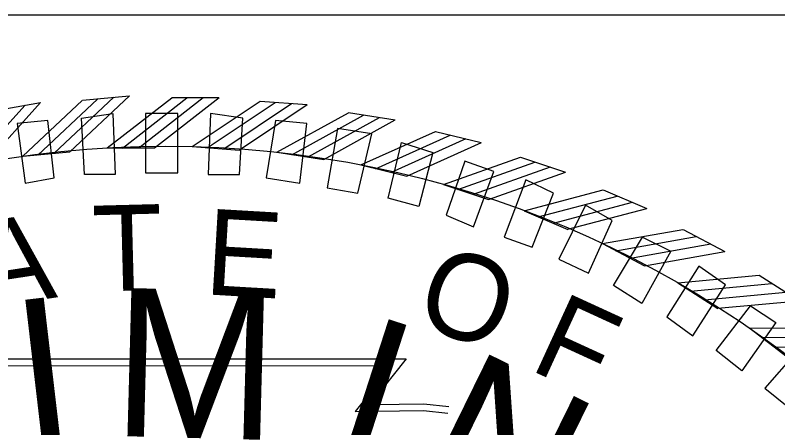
# Model space of a CAD drawing. Extents: x 16 to 1228740, y 11 to 152440.
# Drawn here: x 17.7544 to 17.8153, y 10.9657 to 10.9986 of the extents above; entities that cross this region are included whole.
import ezdxf

# ---------------------------------------------------------------- set-up
doc = ezdxf.new("R2010")
doc.units = 0
for name, color, linetype in [('B_Preliminary', 7, 'Continuous'), ('B_StampERBB', 7, 'Continuous'), ('B_StampHSS', 7, 'Continuous'), ('B_StampJSB', 7, 'Continuous'), ('B_StampSCR', 7, 'Continuous'), ('B_StampSFH', 7, 'Continuous'), ('R_No Plot', 7, 'Continuous')]:
    doc.layers.add(name, color=color, linetype=linetype)

msp = doc.modelspace()

# ---------------------------------------------------------------- linework, layer by layer
at = {"layer": 'B_Preliminary'}
for p, q in [((17.75971, 10.990408), (17.76221, 10.990783)), ((17.76221, 10.990783), (17.762402, 10.985908)), ((17.767402, 10.990783), (17.764835, 10.990783)), ((17.764835, 10.990783), (17.764835, 10.986033)), ((17.767402, 10.986033), (17.767402, 10.990783)), ((17.770027, 10.990783), (17.769835, 10.985908)), ((17.772585, 10.990408), (17.770027, 10.990783)), ((17.757027, 10.990224), (17.754585, 10.989974)), ((17.754585, 10.989974), (17.75521, 10.985224)), ((17.757527, 10.985658), (17.757027, 10.990224)), ((17.75996, 10.985908), (17.75971, 10.990408)), ((17.772335, 10.985908), (17.772585, 10.990408)), ((17.77521, 10.990224), (17.77446, 10.985658)), ((17.77771, 10.989974), (17.77521, 10.990224)), ((17.777152, 10.985224), (17.77771, 10.989974)), ((17.780152, 10.989599), (17.779335, 10.984849)), ((17.782902, 10.989158), (17.780152, 10.989599)), ((17.781777, 10.984408), (17.782902, 10.989158)), ((17.78421, 10.984033), (17.785277, 10.988474)), ((17.785277, 10.988474), (17.787777, 10.987658)), ((17.787777, 10.987658), (17.786652, 10.983349)), ((17.790335, 10.986974), (17.788835, 10.982658)), ((17.792652, 10.986158), (17.790335, 10.986974)), ((17.75521, 10.985224), (17.757527, 10.985658)), ((17.762402, 10.985908), (17.75996, 10.985908)), ((17.764835, 10.986033), (17.767402, 10.986033)), ((17.769835, 10.985908), (17.772335, 10.985908)), ((17.77446, 10.985658), (17.777152, 10.985224)), ((17.791027, 10.981724), (17.792652, 10.986158)), ((17.79521, 10.985474), (17.79346, 10.980908)), ((17.797402, 10.984408), (17.79521, 10.985474)), ((17.779335, 10.984849), (17.781777, 10.984408)), ((17.79571, 10.980099), (17.797402, 10.984408)), ((17.786652, 10.983349), (17.78421, 10.984033)), ((17.79996, 10.983474), (17.797835, 10.979158)), ((17.802085, 10.982224), (17.79996, 10.983474)), ((17.788835, 10.982658), (17.791027, 10.981724)), ((17.80021, 10.978033), (17.802085, 10.982224)), ((17.79346, 10.980908), (17.79571, 10.980099)), ((17.80221, 10.977033), (17.804527, 10.980908)), ((17.804527, 10.980908), (17.806777, 10.979783)), ((17.806777, 10.979783), (17.80446, 10.975599)), ((17.797835, 10.979158), (17.80021, 10.978033)), ((17.809027, 10.978599), (17.80646, 10.974533)), ((17.811152, 10.977099), (17.809027, 10.978599)), ((17.808527, 10.973033), (17.811152, 10.977099)), ((17.80446, 10.975599), (17.80221, 10.977033)), ((17.810402, 10.971849), (17.813152, 10.975408)), ((17.813152, 10.975408), (17.815152, 10.974099)), ((17.80646, 10.974533), (17.808527, 10.973033)), ((17.815152, 10.974099), (17.81246, 10.970224)), ((17.81746, 10.972474), (17.814277, 10.968849)), ((17.81246, 10.970224), (17.810402, 10.971849)), ((17.814277, 10.968849), (17.81621, 10.967283))]:
    msp.add_line(p, q, dxfattribs=at)
at = {"layer": 'B_StampERBB'}
for p, q in [((17.759782, 10.99184), (17.763536, 10.992186)), ((17.766921, 10.99205), (17.770691, 10.99205)), ((17.773983, 10.991767), (17.777742, 10.991491)), ((17.752726, 10.990997), (17.756438, 10.991651)), ((17.78103, 10.990852), (17.784754, 10.990266)), ((17.787978, 10.989358), (17.791641, 10.988467)), ((17.761776, 10.988038), (17.765555, 10.988038)), ((17.768557, 10.988144), (17.772326, 10.987867)), ((17.755027, 10.987373), (17.75879, 10.98772)), ((17.775324, 10.987689), (17.779057, 10.987102)), ((17.794778, 10.987296), (17.798355, 10.986105)), ((17.78203, 10.986678), (17.785702, 10.985784)), ((17.78863, 10.985115), (17.792215, 10.983921)), ((17.801385, 10.984679), (17.804852, 10.983196)), ((17.795078, 10.983014), (17.798552, 10.981528)), ((17.807754, 10.981525), (17.811086, 10.979762)), ((17.80133, 10.980386), (17.80467, 10.978619)), ((17.81384, 10.977856), (17.817015, 10.975824)), ((17.807344, 10.977252), (17.810526, 10.975214)), ((17.813079, 10.973632), (17.816082, 10.971338))]:
    msp.add_line(p, q, dxfattribs=at)
for points in [[(17.755023, 10.987369), (17.759777, 10.991836)], [(17.756232, 10.987469), (17.760986, 10.991936)], [(17.757534, 10.987618), (17.762288, 10.992085)], [(17.758785, 10.987722), (17.763539, 10.992189)], [(17.761772, 10.988035), (17.766915, 10.992046)], [(17.762985, 10.988024), (17.768129, 10.992035)], [(17.764295, 10.988053), (17.769438, 10.992064)], [(17.765551, 10.988041), (17.770694, 10.992053)], [(17.768553, 10.988141), (17.773977, 10.991764)], [(17.769762, 10.988041), (17.775186, 10.991664)], [(17.750833, 10.986604), (17.755202, 10.991448)], [(17.752072, 10.986811), (17.756441, 10.991655)], [(17.77107, 10.987973), (17.776494, 10.991597)], [(17.772322, 10.98787), (17.777746, 10.991493)], [(17.775319, 10.987687), (17.781024, 10.99085)], [(17.776516, 10.987487), (17.782221, 10.99065)], [(17.777814, 10.987312), (17.783519, 10.990475)], [(17.779053, 10.987105), (17.784758, 10.990268)], [(17.782025, 10.986675), (17.787972, 10.989356)], [(17.783201, 10.986377), (17.789148, 10.989058)], [(17.78448, 10.986096), (17.790427, 10.988777)], [(17.785698, 10.985787), (17.791645, 10.988468)], [(17.788624, 10.985113), (17.794772, 10.987294)], [(17.789772, 10.984719), (17.79592, 10.9869)], [(17.791024, 10.984333), (17.797171, 10.986514)], [(17.792211, 10.983925), (17.798359, 10.986106)], [(17.795072, 10.983012), (17.801379, 10.984678)], [(17.796183, 10.982525), (17.80249, 10.98419)], [(17.797399, 10.982036), (17.803706, 10.983702)], [(17.798549, 10.981532), (17.804856, 10.983198)], [(17.801324, 10.980385), (17.807747, 10.981525)], [(17.802392, 10.979808), (17.808815, 10.980947)], [(17.803563, 10.979221), (17.809986, 10.98036)], [(17.804667, 10.978623), (17.81109, 10.979762)], [(17.807338, 10.977251), (17.813834, 10.977856)], [(17.808354, 10.976588), (17.814849, 10.977193)], [(17.809473, 10.975906), (17.815968, 10.976511)], [(17.810524, 10.975219), (17.817019, 10.975824)], [(17.813073, 10.973632), (17.819596, 10.973698)], [(17.814031, 10.972886), (17.820554, 10.972953)], [(17.815089, 10.972114), (17.821612, 10.972181)], [(17.752875, 10.966818), (17.750865, 10.97117), (17.785635, 10.97119), (17.78273, 10.96754), (17.785092, 10.967571), (17.787065, 10.967597), (17.789037, 10.967382)], [(17.753375, 10.967049), (17.751726, 10.97062), (17.784493, 10.970639), (17.781576, 10.966974), (17.785099, 10.96702), (17.787039, 10.967045), (17.788977, 10.966834)]]:
    msp.add_lwpolyline(points, dxfattribs=at)
at = {"layer": 'B_StampHSS'}
for p, q in [((17.759782, 10.99184), (17.763536, 10.992186)), ((17.766921, 10.99205), (17.770691, 10.99205)), ((17.773983, 10.991767), (17.777742, 10.991491)), ((17.752726, 10.990997), (17.756438, 10.991651)), ((17.78103, 10.990852), (17.784754, 10.990266)), ((17.787978, 10.989358), (17.791641, 10.988467)), ((17.761776, 10.988038), (17.765555, 10.988038)), ((17.768557, 10.988144), (17.772326, 10.987867)), ((17.755027, 10.987373), (17.75879, 10.98772)), ((17.775324, 10.987689), (17.779057, 10.987102)), ((17.794778, 10.987296), (17.798355, 10.986105)), ((17.78203, 10.986678), (17.785702, 10.985784)), ((17.78863, 10.985115), (17.792215, 10.983921)), ((17.801385, 10.984679), (17.804852, 10.983196)), ((17.795078, 10.983014), (17.798552, 10.981528)), ((17.807754, 10.981525), (17.811086, 10.979762)), ((17.80133, 10.980386), (17.80467, 10.978619)), ((17.81384, 10.977856), (17.817015, 10.975824)), ((17.807344, 10.977252), (17.810526, 10.975214)), ((17.813079, 10.973632), (17.816082, 10.971338))]:
    msp.add_line(p, q, dxfattribs=at)
for points in [[(17.755023, 10.987369), (17.759777, 10.991836)], [(17.756232, 10.987469), (17.760986, 10.991936)], [(17.757534, 10.987618), (17.762288, 10.992085)], [(17.758785, 10.987722), (17.763539, 10.992189)], [(17.761772, 10.988035), (17.766915, 10.992046)], [(17.762985, 10.988024), (17.768129, 10.992035)], [(17.764295, 10.988053), (17.769438, 10.992064)], [(17.765551, 10.988041), (17.770694, 10.992053)], [(17.768553, 10.988141), (17.773977, 10.991764)], [(17.769762, 10.988041), (17.775186, 10.991664)], [(17.750833, 10.986604), (17.755202, 10.991448)], [(17.752072, 10.986811), (17.756441, 10.991655)], [(17.77107, 10.987973), (17.776494, 10.991597)], [(17.772322, 10.98787), (17.777746, 10.991493)], [(17.775319, 10.987687), (17.781024, 10.99085)], [(17.776516, 10.987487), (17.782221, 10.99065)], [(17.777814, 10.987312), (17.783519, 10.990475)], [(17.779053, 10.987105), (17.784758, 10.990268)], [(17.782025, 10.986675), (17.787972, 10.989356)], [(17.783201, 10.986377), (17.789148, 10.989058)], [(17.78448, 10.986096), (17.790427, 10.988777)], [(17.785698, 10.985787), (17.791645, 10.988468)], [(17.788624, 10.985113), (17.794772, 10.987294)], [(17.789772, 10.984719), (17.79592, 10.9869)], [(17.791024, 10.984333), (17.797171, 10.986514)], [(17.792211, 10.983925), (17.798359, 10.986106)], [(17.795072, 10.983012), (17.801379, 10.984678)], [(17.796183, 10.982525), (17.80249, 10.98419)], [(17.797399, 10.982036), (17.803706, 10.983702)], [(17.798549, 10.981532), (17.804856, 10.983198)], [(17.801324, 10.980385), (17.807747, 10.981525)], [(17.802392, 10.979808), (17.808815, 10.980947)], [(17.803563, 10.979221), (17.809986, 10.98036)], [(17.804667, 10.978623), (17.81109, 10.979762)], [(17.807338, 10.977251), (17.813834, 10.977856)], [(17.808354, 10.976588), (17.814849, 10.977193)], [(17.809473, 10.975906), (17.815968, 10.976511)], [(17.810524, 10.975219), (17.817019, 10.975824)], [(17.813073, 10.973632), (17.819596, 10.973698)], [(17.814031, 10.972886), (17.820554, 10.972953)], [(17.815089, 10.972114), (17.821612, 10.972181)], [(17.752875, 10.966818), (17.750865, 10.97117), (17.785635, 10.97119), (17.78273, 10.96754), (17.785092, 10.967571), (17.787065, 10.967597), (17.789037, 10.967382)], [(17.753375, 10.967049), (17.751726, 10.97062), (17.784493, 10.970639), (17.781576, 10.966974), (17.785099, 10.96702), (17.787039, 10.967045), (17.788977, 10.966834)]]:
    msp.add_lwpolyline(points, dxfattribs=at)
at = {"layer": 'B_StampJSB'}
for p, q in [((17.759782, 10.99184), (17.763536, 10.992186)), ((17.766921, 10.99205), (17.770691, 10.99205)), ((17.773983, 10.991767), (17.777742, 10.991491)), ((17.752726, 10.990997), (17.756438, 10.991651)), ((17.78103, 10.990852), (17.784754, 10.990266)), ((17.787978, 10.989358), (17.791641, 10.988467)), ((17.761776, 10.988038), (17.765555, 10.988038)), ((17.768557, 10.988144), (17.772326, 10.987867)), ((17.755027, 10.987373), (17.75879, 10.98772)), ((17.775324, 10.987689), (17.779057, 10.987102)), ((17.794778, 10.987296), (17.798355, 10.986105)), ((17.78203, 10.986678), (17.785702, 10.985784)), ((17.78863, 10.985115), (17.792215, 10.983921)), ((17.801385, 10.984679), (17.804852, 10.983196)), ((17.795078, 10.983014), (17.798552, 10.981528)), ((17.807754, 10.981525), (17.811086, 10.979762)), ((17.80133, 10.980386), (17.80467, 10.978619)), ((17.81384, 10.977856), (17.817015, 10.975824)), ((17.807344, 10.977252), (17.810526, 10.975214)), ((17.813079, 10.973632), (17.816082, 10.971338))]:
    msp.add_line(p, q, dxfattribs=at)
for points in [[(17.755023, 10.987369), (17.759777, 10.991836)], [(17.756232, 10.987469), (17.760986, 10.991936)], [(17.757534, 10.987618), (17.762288, 10.992085)], [(17.758785, 10.987722), (17.763539, 10.992189)], [(17.761772, 10.988035), (17.766915, 10.992046)], [(17.762985, 10.988024), (17.768129, 10.992035)], [(17.764295, 10.988053), (17.769438, 10.992064)], [(17.765551, 10.988041), (17.770694, 10.992053)], [(17.768553, 10.988141), (17.773977, 10.991764)], [(17.769762, 10.988041), (17.775186, 10.991664)], [(17.750833, 10.986604), (17.755202, 10.991448)], [(17.752072, 10.986811), (17.756441, 10.991655)], [(17.77107, 10.987973), (17.776494, 10.991597)], [(17.772322, 10.98787), (17.777746, 10.991493)], [(17.775319, 10.987687), (17.781024, 10.99085)], [(17.776516, 10.987487), (17.782221, 10.99065)], [(17.777814, 10.987312), (17.783519, 10.990475)], [(17.779053, 10.987105), (17.784758, 10.990268)], [(17.782025, 10.986675), (17.787972, 10.989356)], [(17.783201, 10.986377), (17.789148, 10.989058)], [(17.78448, 10.986096), (17.790427, 10.988777)], [(17.785698, 10.985787), (17.791645, 10.988468)], [(17.788624, 10.985113), (17.794772, 10.987294)], [(17.789772, 10.984719), (17.79592, 10.9869)], [(17.791024, 10.984333), (17.797171, 10.986514)], [(17.792211, 10.983925), (17.798359, 10.986106)], [(17.795072, 10.983012), (17.801379, 10.984678)], [(17.796183, 10.982525), (17.80249, 10.98419)], [(17.797399, 10.982036), (17.803706, 10.983702)], [(17.798549, 10.981532), (17.804856, 10.983198)], [(17.801324, 10.980385), (17.807747, 10.981525)], [(17.802392, 10.979808), (17.808815, 10.980947)], [(17.803563, 10.979221), (17.809986, 10.98036)], [(17.804667, 10.978623), (17.81109, 10.979762)], [(17.807338, 10.977251), (17.813834, 10.977856)], [(17.808354, 10.976588), (17.814849, 10.977193)], [(17.809473, 10.975906), (17.815968, 10.976511)], [(17.810524, 10.975219), (17.817019, 10.975824)], [(17.813073, 10.973632), (17.819596, 10.973698)], [(17.814031, 10.972886), (17.820554, 10.972953)], [(17.815089, 10.972114), (17.821612, 10.972181)], [(17.752875, 10.966818), (17.750865, 10.97117), (17.785635, 10.97119), (17.78273, 10.96754), (17.785092, 10.967571), (17.787065, 10.967597), (17.789037, 10.967382)], [(17.753375, 10.967049), (17.751726, 10.97062), (17.784493, 10.970639), (17.781576, 10.966974), (17.785099, 10.96702), (17.787039, 10.967045), (17.788977, 10.966834)]]:
    msp.add_lwpolyline(points, dxfattribs=at)
msp.add_circle((17.766447, 10.906117), 0.082054, dxfattribs=at)
at = {"layer": 'B_StampSCR'}
for p, q in [((17.759782, 10.99184), (17.763536, 10.992186)), ((17.766921, 10.99205), (17.770691, 10.99205)), ((17.773983, 10.991767), (17.777742, 10.991491)), ((17.752726, 10.990997), (17.756438, 10.991651)), ((17.78103, 10.990852), (17.784754, 10.990266)), ((17.787978, 10.989358), (17.791641, 10.988467)), ((17.761776, 10.988038), (17.765555, 10.988038)), ((17.768557, 10.988144), (17.772326, 10.987867)), ((17.755027, 10.987373), (17.75879, 10.98772)), ((17.775324, 10.987689), (17.779057, 10.987102)), ((17.794778, 10.987296), (17.798355, 10.986105)), ((17.78203, 10.986678), (17.785702, 10.985784)), ((17.78863, 10.985115), (17.792215, 10.983921)), ((17.801385, 10.984679), (17.804852, 10.983196)), ((17.795078, 10.983014), (17.798552, 10.981528)), ((17.807754, 10.981525), (17.811086, 10.979762)), ((17.80133, 10.980386), (17.80467, 10.978619)), ((17.81384, 10.977856), (17.817015, 10.975824)), ((17.807344, 10.977252), (17.810526, 10.975214)), ((17.813079, 10.973632), (17.816082, 10.971338))]:
    msp.add_line(p, q, dxfattribs=at)
for points in [[(17.755023, 10.987369), (17.759777, 10.991836)], [(17.756232, 10.987469), (17.760986, 10.991936)], [(17.757534, 10.987618), (17.762288, 10.992085)], [(17.758785, 10.987722), (17.763539, 10.992189)], [(17.761772, 10.988035), (17.766915, 10.992046)], [(17.762985, 10.988024), (17.768129, 10.992035)], [(17.764295, 10.988053), (17.769438, 10.992064)], [(17.765551, 10.988041), (17.770694, 10.992053)], [(17.768553, 10.988141), (17.773977, 10.991764)], [(17.769762, 10.988041), (17.775186, 10.991664)], [(17.750833, 10.986604), (17.755202, 10.991448)], [(17.752072, 10.986811), (17.756441, 10.991655)], [(17.77107, 10.987973), (17.776494, 10.991597)], [(17.772322, 10.98787), (17.777746, 10.991493)], [(17.775319, 10.987687), (17.781024, 10.99085)], [(17.776516, 10.987487), (17.782221, 10.99065)], [(17.777814, 10.987312), (17.783519, 10.990475)], [(17.779053, 10.987105), (17.784758, 10.990268)], [(17.782025, 10.986675), (17.787972, 10.989356)], [(17.783201, 10.986377), (17.789148, 10.989058)], [(17.78448, 10.986096), (17.790427, 10.988777)], [(17.785698, 10.985787), (17.791645, 10.988468)], [(17.788624, 10.985113), (17.794772, 10.987294)], [(17.789772, 10.984719), (17.79592, 10.9869)], [(17.791024, 10.984333), (17.797171, 10.986514)], [(17.792211, 10.983925), (17.798359, 10.986106)], [(17.795072, 10.983012), (17.801379, 10.984678)], [(17.796183, 10.982525), (17.80249, 10.98419)], [(17.797399, 10.982036), (17.803706, 10.983702)], [(17.798549, 10.981532), (17.804856, 10.983198)], [(17.801324, 10.980385), (17.807747, 10.981525)], [(17.802392, 10.979808), (17.808815, 10.980947)], [(17.803563, 10.979221), (17.809986, 10.98036)], [(17.804667, 10.978623), (17.81109, 10.979762)], [(17.807338, 10.977251), (17.813834, 10.977856)], [(17.808354, 10.976588), (17.814849, 10.977193)], [(17.809473, 10.975906), (17.815968, 10.976511)], [(17.810524, 10.975219), (17.817019, 10.975824)], [(17.813073, 10.973632), (17.819596, 10.973698)], [(17.814031, 10.972886), (17.820554, 10.972953)], [(17.815089, 10.972114), (17.821612, 10.972181)], [(17.752875, 10.966818), (17.750865, 10.97117), (17.785635, 10.97119), (17.78273, 10.96754), (17.785092, 10.967571), (17.787065, 10.967597), (17.789037, 10.967382)], [(17.753375, 10.967049), (17.751726, 10.97062), (17.784493, 10.970639), (17.781576, 10.966974), (17.785099, 10.96702), (17.787039, 10.967045), (17.788977, 10.966834)]]:
    msp.add_lwpolyline(points, dxfattribs=at)
at = {"layer": 'B_StampSFH'}
for p, q in [((17.759782, 10.99184), (17.763536, 10.992186)), ((17.766921, 10.99205), (17.770691, 10.99205)), ((17.773983, 10.991767), (17.777742, 10.991491)), ((17.752726, 10.990997), (17.756438, 10.991651)), ((17.78103, 10.990852), (17.784754, 10.990266)), ((17.787978, 10.989358), (17.791641, 10.988467)), ((17.761776, 10.988038), (17.765555, 10.988038)), ((17.768557, 10.988144), (17.772326, 10.987867)), ((17.755027, 10.987373), (17.75879, 10.98772)), ((17.775324, 10.987689), (17.779057, 10.987102)), ((17.794778, 10.987296), (17.798355, 10.986105)), ((17.78203, 10.986678), (17.785702, 10.985784)), ((17.78863, 10.985115), (17.792215, 10.983921)), ((17.801385, 10.984679), (17.804852, 10.983196)), ((17.795078, 10.983014), (17.798552, 10.981528)), ((17.807754, 10.981525), (17.811086, 10.979762)), ((17.80133, 10.980386), (17.80467, 10.978619)), ((17.81384, 10.977856), (17.817015, 10.975824)), ((17.807344, 10.977252), (17.810526, 10.975214)), ((17.813079, 10.973632), (17.816082, 10.971338))]:
    msp.add_line(p, q, dxfattribs=at)
for points in [[(17.755023, 10.987369), (17.759777, 10.991836)], [(17.756232, 10.987469), (17.760986, 10.991936)], [(17.757534, 10.987618), (17.762288, 10.992085)], [(17.758785, 10.987722), (17.763539, 10.992189)], [(17.761772, 10.988035), (17.766915, 10.992046)], [(17.762985, 10.988024), (17.768129, 10.992035)], [(17.764295, 10.988053), (17.769438, 10.992064)], [(17.765551, 10.988041), (17.770694, 10.992053)], [(17.768553, 10.988141), (17.773977, 10.991764)], [(17.769762, 10.988041), (17.775186, 10.991664)], [(17.750833, 10.986604), (17.755202, 10.991448)], [(17.752072, 10.986811), (17.756441, 10.991655)], [(17.77107, 10.987973), (17.776494, 10.991597)], [(17.772322, 10.98787), (17.777746, 10.991493)], [(17.775319, 10.987687), (17.781024, 10.99085)], [(17.776516, 10.987487), (17.782221, 10.99065)], [(17.777814, 10.987312), (17.783519, 10.990475)], [(17.779053, 10.987105), (17.784758, 10.990268)], [(17.782025, 10.986675), (17.787972, 10.989356)], [(17.783201, 10.986377), (17.789148, 10.989058)], [(17.78448, 10.986096), (17.790427, 10.988777)], [(17.785698, 10.985787), (17.791645, 10.988468)], [(17.788624, 10.985113), (17.794772, 10.987294)], [(17.789772, 10.984719), (17.79592, 10.9869)], [(17.791024, 10.984333), (17.797171, 10.986514)], [(17.792211, 10.983925), (17.798359, 10.986106)], [(17.795072, 10.983012), (17.801379, 10.984678)], [(17.796183, 10.982525), (17.80249, 10.98419)], [(17.797399, 10.982036), (17.803706, 10.983702)], [(17.798549, 10.981532), (17.804856, 10.983198)], [(17.801324, 10.980385), (17.807747, 10.981525)], [(17.802392, 10.979808), (17.808815, 10.980947)], [(17.803563, 10.979221), (17.809986, 10.98036)], [(17.804667, 10.978623), (17.81109, 10.979762)], [(17.807338, 10.977251), (17.813834, 10.977856)], [(17.808354, 10.976588), (17.814849, 10.977193)], [(17.809473, 10.975906), (17.815968, 10.976511)], [(17.810524, 10.975219), (17.817019, 10.975824)], [(17.813073, 10.973632), (17.819596, 10.973698)], [(17.814031, 10.972886), (17.820554, 10.972953)], [(17.815089, 10.972114), (17.821612, 10.972181)], [(17.752875, 10.966818), (17.750865, 10.97117), (17.785635, 10.97119), (17.78273, 10.96754), (17.785092, 10.967571), (17.787065, 10.967597), (17.789037, 10.967382)], [(17.753375, 10.967049), (17.751726, 10.97062), (17.784493, 10.970639), (17.781576, 10.966974), (17.785099, 10.96702), (17.787039, 10.967045), (17.788977, 10.966834)]]:
    msp.add_lwpolyline(points, dxfattribs=at)
at = {"layer": 'R_No Plot'}
msp.add_line((17.887998, 10.998635), (17.47349, 10.998635), dxfattribs=at)

# ---------------------------------------------------------------- texts
at = {"layer": 'B_Preliminary'}
for s, rotation, p in [('M', 358.46666, (17.762085, 10.965033)), ('I', 6.67523, (17.755152, 10.963974)), ('I', 342.04953, (17.77921, 10.963533)), ('N', 333.84096, (17.785902, 10.961474))]:
    msp.add_text(s, height=0.011841, rotation=rotation, dxfattribs=at).set_placement(p)
at = {"layer": 'B_StampERBB'}
for s, rotation, p in [('T', 1.47887, (17.760672, 10.976553)), ('E', 356.67203, (17.769449, 10.976345)), ('A', 8.67877, (17.751815, 10.975189)), ('O', 341.2218, (17.786102, 10.973993)), ('F', 335.36282, (17.795346, 10.970378))]:
    msp.add_text(s, height=0.006859, rotation=rotation, dxfattribs=at).set_placement(p)
at = {"layer": 'B_StampHSS'}
for s, rotation, p in [('T', 1.47887, (17.760672, 10.976553)), ('E', 356.67203, (17.769449, 10.976345)), ('A', 8.67877, (17.751815, 10.975189)), ('O', 341.2218, (17.786102, 10.973993)), ('F', 335.36282, (17.795346, 10.970378))]:
    msp.add_text(s, height=0.006859, rotation=rotation, dxfattribs=at).set_placement(p)
at = {"layer": 'B_StampJSB'}
for s, rotation, p in [('T', 1.47887, (17.760672, 10.976553)), ('E', 356.67203, (17.769449, 10.976345)), ('A', 8.67877, (17.751815, 10.975189)), ('O', 341.2218, (17.786102, 10.973993)), ('F', 335.36282, (17.795346, 10.970378))]:
    msp.add_text(s, height=0.006859, rotation=rotation, dxfattribs=at).set_placement(p)
at = {"layer": 'B_StampSCR'}
for s, rotation, p in [('T', 1.47887, (17.760672, 10.976553)), ('E', 356.67203, (17.769449, 10.976345)), ('A', 8.67877, (17.751815, 10.975189)), ('O', 341.2218, (17.786102, 10.973993)), ('F', 335.36282, (17.795346, 10.970378))]:
    msp.add_text(s, height=0.006859, rotation=rotation, dxfattribs=at).set_placement(p)
at = {"layer": 'B_StampSFH'}
for s, rotation, p in [('T', 1.47887, (17.760672, 10.976553)), ('E', 356.67203, (17.769449, 10.976345)), ('A', 8.67877, (17.751815, 10.975189)), ('O', 341.2218, (17.786102, 10.973993)), ('F', 335.36282, (17.795346, 10.970378))]:
    msp.add_text(s, height=0.006859, rotation=rotation, dxfattribs=at).set_placement(p)

doc.saveas('drawing.dxf')
